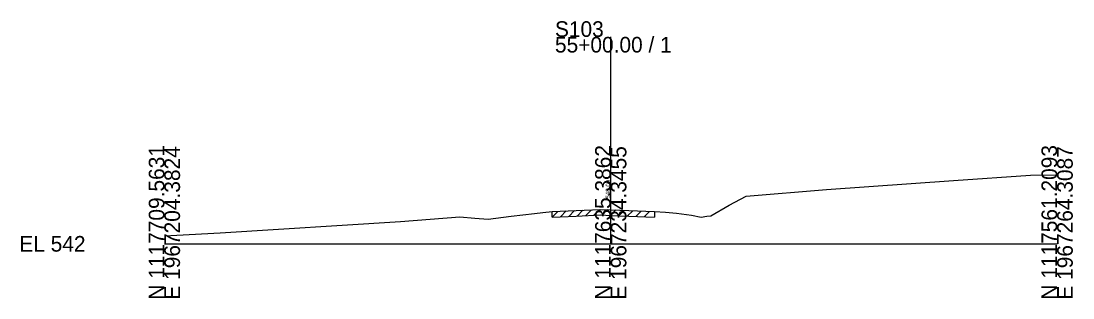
# Model space of a CAD drawing. Extents: x -26 to 163, y -10 to 24018.
# Drawn here: x -25.7 to 162.8, y 4490.3 to 4539.9 of the extents above; entities that cross this region are included whole.
import ezdxf

# ---------------------------------------------------------------- set-up
doc = ezdxf.new("R2010")
doc.units = 0
for name, color, linetype in [('RD_GPK_XS_Cell', 7, 'Continuous'), ('RD_XS_ExGround', 7, 'Continuous'), ('RD_XS_ExPaveRet', 7, 'Continuous'), ('RD_XS_TX_Elev_EX', 7, 'Continuous')]:
    doc.layers.add(name, color=color, linetype=linetype)

msp = doc.modelspace()

# ---------------------------------------------------------------- linework, layer by layer
at = {"layer": 'RD_GPK_XS_Cell'}
for p, q in [((80, 4500), (80, 4537.06)), ((0, 4500), (80, 4500)), ((80, 4500), (160, 4500))]:
    msp.add_line(p, q, dxfattribs=at)
at = {"layer": 'RD_XS_ExGround'}
msp.add_lwpolyline([(0, 4501.43), (9.98, 4501.94), (42.33, 4503.98), (52.93, 4504.81), (55.66, 4504.6), (58.05, 4504.42), (62.15, 4504.96), (66.31, 4505.46), (67.84, 4505.61), (69.47, 4505.76), (73.8, 4505.96), (78.18, 4506.17), (80, 4506.09), (83.27, 4505.96), (87.83, 4505.77), (89.84, 4505.65), (91.8, 4505.5), (94.47, 4505.11), (96.19, 4504.78), (97.24, 4504.93), (97.94, 4505.03), (101.23, 4506.94), (104.29, 4508.55), (118.66, 4509.75), (141.43, 4511.33), (155.24, 4512.31), (160, 4512.35)], dxfattribs=at)
at = {"layer": 'RD_XS_ExPaveRet'}
for p, q in [((72.47, 4504.9), (73.52, 4505.95)), ((73.97, 4504.97), (75.02, 4506.02)), ((75.47, 4505.04), (76.52, 4506.09)), ((76.97, 4505.11), (78.02, 4506.16)), ((78.47, 4505.16), (79.43, 4506.12)), ((79.97, 4505.09), (80.93, 4506.06)), ((81.47, 4505.03), (82.43, 4505.99)), ((82.97, 4504.97), (83.93, 4505.93)), ((69.47, 4504.76), (70.52, 4505.81)), ((69.47, 4504.76), (69.47, 4505.76)), ((69.47, 4504.76), (73.8, 4504.96)), ((70.97, 4504.83), (72.02, 4505.88)), ((73.8, 4504.96), (78.18, 4505.17)), ((78.18, 4505.17), (80, 4505.09)), ((80, 4505.09), (83.27, 4504.96)), ((83.27, 4504.96), (87.83, 4504.77)), ((84.47, 4504.91), (85.43, 4505.87)), ((85.97, 4504.85), (86.93, 4505.81)), ((87.83, 4505.77), (87.83, 4504.77))]:
    msp.add_line(p, q, dxfattribs=at)

# ---------------------------------------------------------------- texts
at = {"layer": 'RD_GPK_XS_Cell'}
for s, p in [('S103', (70, 4537.06)), ('55+00.00 / 1', (70, 4534.26)), ('EL 542', (-26, 4498.6))]:
    msp.add_text(s, height=2.8, dxfattribs=at).set_placement(p)
for s, p in [('N 1117709.5631', (0, 4490)), ('E 1967204.3824', (2.8, 4490)), ('N 1117635.3862', (80, 4490)), ('E 1967234.3455', (82.8, 4490)), ('N 1117561.2093', (160, 4490)), ('E 1967264.3087', (162.8, 4490))]:
    msp.add_text(s, height=2.8, rotation=90, dxfattribs=at).set_placement(p)
at = {"layer": 'RD_XS_TX_Elev_EX'}
msp.add_text('548.09', height=0.8, rotation=90, dxfattribs=at).set_placement((79.9, 4508.09))

doc.saveas('drawing.dxf')
